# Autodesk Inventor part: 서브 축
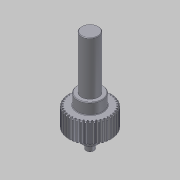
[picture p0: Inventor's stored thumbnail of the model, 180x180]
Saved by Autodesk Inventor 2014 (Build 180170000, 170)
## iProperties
Created: 2014-07
Part Number: 서브 축
Material: 강
Document SubType Name: Modeling
Designer: KYOUNG IL JANG
Categories: <?xml version="1.0" encoding="UTF-16"?> <MemberInstance><Categories><FamilyTemplate><FamilyTemplateParameter ValueType="xs:double" Id="1" ObjectReferenceKey="da
Density: 1 g/cm^3
Appearance: 강철
CustomPartVersion: 1
Company: 한국ATC센터
Author: KYOUNG IL JANG
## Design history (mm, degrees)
sketch "Sketch1"
  geometry: C1 r 21 at (0, 0)
  constraints: 1 centre point
  dimensions: "d0" = 42 diameter of C1 (= da_da)
extrude "Extrusion1" new body sketch "Sketch1" distance "d1" = 20 (= da_b); taper "d2" = 0 deg
workplane "Work Plane2"
feature "피치 지름" dims "d4" = 10, "d5" = 0
workplane "Work Plane8"
workplane "Work Plane9"
chamfer "모따기1" distance "d49" = 1; stored, may be unused: second distance "d50" = 2, angle "d51" = 45 deg
sketch "스케치3"
  geometry: C1 r 12.5 at (0, 0); 1 further point
  constraints: 1 centre point, 1 coincident
  dimensions: "d52" = 25 diameter of C1
extrude "돌출2" join sketch "스케치3" distance "d53" = 11; taper "d54" = 0 deg
sketch "스케치4"
  geometry: C1 r 8.5 at (0, 0); 1 further point
  constraints: 1 centre point, 1 coincident
  dimensions: "d55" = 17 diameter of C1
extrude "돌출3" join sketch "스케치4" distance "d56" = 53; taper "d57" = 0 deg
sketch "스케치5"
  geometry: C1 r 7.5 at (0, 0); 1 further point
  constraints: 1 centre point, 1 coincident
  dimensions: "d62" = 15 diameter of C1
extrude "돌출4" join sketch "스케치5" distance "d63" = 11; taper "d64" = 0 deg
sketch "스케치6"
  geometry: C1 r 4 at (0, 0); 1 further point
  constraints: 1 centre point, 1 coincident
  dimensions: "d65" = 8 diameter of C1
extrude "돌출5" join sketch "스케치6" distance "d66" = 7; taper "d67" = 0 deg
chamfer "모따기2" distance "d58" = 0.5; stored, may be unused: second distance "d59" = 2, angle "d60" = 45 deg
fillet "모깎기1" dims "d61" = 0.5
feature "스퍼 기어" dims "da_b" = 20, "da_d" = 40, "da_aw" = 31, "da_da" = 42, "da_df" = 37.5, "da_dw" = 40, angle "da_beta" = 0 deg, "da_lefttooth" = 0, "da_righttooth" = 0
body "Solid1"
sketch "Sketch2"
  geometry: C1 r 21 at (0, 0) reference; C2 r 20 at (0, 0)
  constraints: 1 centre point, 1 coincident
  dimensions: "d3" = 40 diameter of C2 (= da_dw)
body "Srf1"
other parameters: "d16" = 31 (= da_aw), "d17" = 0, "d34" = 4.5 deg (computed from da_z), "d39" = 0, "d41" = 0, "d43" = 31 (= da_aw), "d46" = 31 (= da_aw), "d47" = 0, "d48" = 0
